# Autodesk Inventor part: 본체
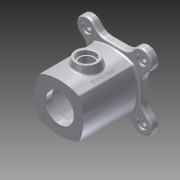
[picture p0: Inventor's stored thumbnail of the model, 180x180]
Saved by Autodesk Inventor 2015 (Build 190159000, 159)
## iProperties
Created: 2016-05
Part Number: 본체
Material: 알루미늄 6061
Document SubType Name: Modeling
Designer: Administrator
Density: 2.7 g/cm^3
Appearance: 알루미늄 - 평지
Mass: 1105.19 g
Surface Area: 862.501 cm^2
Volume: 409.328 cm^3
Author: Administrator
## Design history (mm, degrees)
sketch "스케치1"
  geometry: A1 r 86 centre (43, -0.046) between (-35.369, 35.371) and (-35.409, -35.372); A2 r 86 centre (0.043, -43) between (35.347, 35.42) and (-35.369, 35.371); A3 r 86 centre (-43, -0.046) between (35.409, -35.372) and (35.347, 35.42); A4 r 86 centre (0, 43) between (-35.409, -35.372) and (35.409, -35.372); 1 further point
  constraints: 8 point on circle, 4 centre point
  dimensions: "d103" = 86 distance of A3.centre A1.centre; "d104" = 43 distance of A3.centre point (0, 0); "d105" = 43 distance of A1.centre point (0, 0); "d106" = 86 radius of A2; "d107" = 86 radius of A1; "d108" = 86 radius of A3; "d109" = 86 radius of A4; "d110" = 86 distance of A2.centre A4.centre; "d111" = 43 distance of point (0, 0) A4.centre
extrude "돌출1" new body sketch "스케치1" distance "d12" = 98; taper "d13" = 0 deg
sketch "스케치2"
  geometry: L1 (-14.162, -49)-(14.162, -49); L2 (49, -14.162)-(49, 14.162); L3 (14.162, 49)-(-14.162, 49); L4 (-49, 14.162)-(-49, -14.162); L5 (0, 0)-(-70, -70); L6 (0, 0)-(98.995, 0); L7 (0, 0)-(-81.178, 81.178); L8 (0, 0)-(114.803, 0); L9 (0, 0)-(88.016, 88.016); L10 (0, 0)-(124.473, 0); L11 (0, 0)-(82.092, -82.092); L12 (0, 0)-(116.096, 0); A1 r 18 centre (49.497, 49.497) between (59.754, 34.706) and (34.706, 59.754); A2 r 25 centre (74, 14.162) between (59.754, 34.706) and (49, 14.162); A3 r 25 centre (14.162, 74) between (14.162, 49) and (34.706, 59.754); A4 r 18 centre (-49.497, 49.497) between (-34.706, 59.754) and (-59.754, 34.706); A5 r 18 centre (-49.497, -49.497) between (-59.754, -34.706) and (-34.706, -59.754); A6 r 18 centre (49.497, -49.497) between (34.706, -59.754) and (59.754, -34.706); A7 r 25 centre (-74, 14.162) between (-49, 14.162) and (-59.754, 34.706); A8 r 25 centre (-14.162, 74) between (-34.706, 59.754) and (-14.162, 49); A9 r 25 centre (14.162, -74) between (34.706, -59.754) and (14.162, -49); A10 r 25 centre (74, -14.162) between (49, -14.162) and (59.754, -34.706); A11 r 70 centre (0, 0) between (-49.497, -49.497) and (49.497, 49.497); A12 r 25 centre (-74, -14.162) between (-59.754, -34.706) and (-49, -14.162); A13 r 25 centre (-14.162, -74) between (-14.162, -49) and (-34.706, -59.754); 9 further points
  constraints: 38 point on circle, 24 end point, 16 tangent, 13 centre point, 12 point on line, 5 horizontal, 4 equal length, 4 equal radius, 2 parallel, 1 coincident, 1 perpendicular
  dimensions: "d16" = 36 diameter of A1; "d19" = 25 radius of A2; "d20" = 36 diameter of A4; "d21" = 36 diameter of A5; "d22" = 36 diameter of A6; "d23" = 25 radius of A7; "d92" = 140 diameter of A11; "d93" = 25 radius of A12; "d94" = 25 radius of A13; "d95" = 49 distance from line of point (0, 0) L3; "d96" = 49 distance from line of point (0, 0) L2; "d97" = 49 distance from line of L4 point (0, 0); "d98" = 49 distance from line of L1 point (0, 0); "d99" = 135 deg angle of L5 L6; "d100" = 135 deg angle of L8 L7; "d101" = 45 deg angle of L10 L9; "d102" = 45 deg angle of L11 L12
extrude "돌출2" join sketch "스케치2" distance "d24" = 12; taper "d25" = 0 deg
sketch "스케치3"
  geometry: L1 (0, 0)-(25, 0); L2 (25, 0)-(25, 12); L3 (25, 12)-(0, 12); L4 (0, 12)-(0, 0); L5 (14.162, 110)-(34.706, 110) reference; L6 (-14.162, 110)-(14.162, 110) reference; L7 (0, 12)-(32, 12); L8 (35, 15)-(35, 95); L9 (32, 98)-(0, 98); L10 (0, 98)-(0, 12); L11 (0, 98)-(25, 98); L12 (25, 98)-(25, 110); L13 (25, 110)-(0, 110); L14 (0, 110)-(0, 98); A1 r 3 centre (32, 15) between (32, 12) and (35, 15); A2 r 3 centre (32, 95) between (35, 95) and (32, 98)
  constraints: 24 end point, 6 parallel, 4 point on circle, 4 tangent, 3 horizontal, 3 perpendicular, 2 centre point, 1 equal radius, 1 point on line
  dimensions: "d26" = 12 distance of L1.end L2.end; "d27" = 12 distance of L11.end L12.end; "d28" = 25 distance between parallel lines of L12 L14; "d29" = 35 distance between parallel lines of L10 L8; "d30" = 25 distance between parallel lines of L4 L2; "d31" = 3 radius of A1
revolve "회전1" sketch "스케치3" stored, may be unused: angle "d32" = 90 deg
chamfer "모따기1" distance "d33" = 1; stored, may be unused: second distance "d34" = 2, angle "d35" = 45 deg
sketch "스케치4"
  geometry: L1 (55, 69)-(55, 49); L2 (55, 49)-(40.065, 49); L3 (40.065, 49)-(40.065, 71.633); L4 (43, 0)-(43, 98) reference; L5 (55, 69)-(40.065, 71.633); 1 further point
  constraints: 8 end point, 1 parallel
  dimensions: "d36" = 55 distance from line of L1 point (0, 0); "d37" = 100 deg angle of L4 L5; "d39" = 49 distance from line of point (0, 0) L2; "d91" = 20 distance of L1.start L1.end
revolve "회전2" sketch "스케치4" stored, may be unused: angle "d40" = 90 deg
sketch "스케치5"
  geometry: C1 r 20 at (0, 0) reference; 1 further point
hole "구멍1" sketch "스케치5" at (0, 0) diameter "d41" = 25; stored, may be unused: countersink angle "d45" = 90 deg, drill point angle "d47" = 118 deg; dims "d42" = 6, "d43" = 30, "d44" = 8, "d46" = 30
chamfer "모따기2" distance "d48" = 1; stored, may be unused: second distance "d49" = 2, angle "d50" = 45 deg
fillet "모깎기1" dims "d51" = 3
fillet "모깎기2" dims "d52" = 3
sketch "스케치6"
  geometry: A1 r 15 centre (49.497, 49.497) between (58.045, 37.171) and (37.171, 58.045) reference; A2 r 15 centre (-49.497, 49.497) between (-37.171, 58.045) and (-58.045, 37.171) reference; A3 r 15 centre (-49.497, -49.497) between (-58.045, -37.171) and (-37.171, -58.045) reference; 6 further points
  constraints: 1 other
hole "구멍2" sketch "스케치6" at (49.497, 49.497), (-49.497, 49.497), (-49.497, -49.497), (49.497, -49.497) diameter "d53" = 10; stored, may be unused: countersink angle "d57" = 90 deg, drill point angle "d59" = 118 deg; dims "d54" = 6, "d55" = 18, "d56" = 4, "d58" = 30
sketch "스케치7" dims "d60" = 80
  geometry: L1 (0, 0)-(94.446, 0); C1 r 26 at (0, 0) reference; 4 further points
  constraints: 2 end point, 1 coincident, 1 horizontal, 8 other
  dimensions: "d64" = 360 deg dimension on C1.centre point (28.284, -28.284) (derived)
hole "구멍3" sketch "스케치7" at (28.284, -28.284), (28.284, 28.284), (-28.284, 28.284), (-28.284, -28.284) diameter "d66" = 3.242; stored, may be unused: countersink angle "d70" = 90 deg, drill point angle "d72" = 118 deg; dims "d67" = 7, "d68" = 18, "d69" = 4, "d71" = 10
sketch "스케치8" dims "d73" = 80
  geometry: L1 (0, 0)-(48.585, 0); C1 r 26 at (0, 0) reference; 4 further points
  constraints: 2 end point, 1 coincident, 1 horizontal, 8 other
  dimensions: "d77" = 360 deg dimension on C1.centre point (28.284, 28.284) (derived)
hole "구멍4" sketch "스케치8" at (28.284, 28.284), (-28.284, 28.284), (-28.284, -28.284), (28.284, -28.284) diameter "d79" = 3.242; stored, may be unused: countersink angle "d83" = 90 deg, drill point angle "d85" = 118 deg; dims "d80" = 7, "d81" = 18, "d82" = 4, "d84" = 10
node "작업 평면1"
sketch "스케치9"
  geometry: 2 further points
  constraints: 1 other
  dimensions: "d87" = 29 horizontal distance of point (0, 0) point (29, 49); "d88" = 49 vertical distance of point (0, 0) point (29, 49)
feature "엠보싱1" sketch "스케치9" dims "d89" = 0.5, "d90" = 0, "d103" = 86, "d104" = 43, "d105" = 43, "d106" = 86, "d107" = 86, "d108" = 86, "d109" = 86, "d110" = 86, "d111" = 43
node "솔리드1"
other parameters: "d86" = -43
